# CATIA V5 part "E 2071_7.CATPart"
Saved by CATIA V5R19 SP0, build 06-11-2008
Nomenclature: E 2071_7
Description: PART-E 2071_7-DESC
Property "Hersteller": "Meusburger"
Property "Material": "St"
Property "Bestellnummer": "E 2071/7"
Property "Teilenummer": "E 2071/7"
Property "Beschreibung": "Kugelverschlussstopfen _ Expander sealing plug"
Material "Steel": density 7860 kg/m3, Young's modulus 2e+11 Pa, Poisson ratio 0.266, thermal expansion 1.17e-05 1/K
Bounding box of the stored display mesh (mm): x -3.5 to 3.5, y -3.49 to 3.49, z 0 to 7.5
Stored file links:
  G:\UTB\Kombinované\Bakalářská práce\Catia\FORMA\E 2071_7.CATPart
  D:\Aplikace\CATIA\Nová složka\win_b64\startup\materials\Catalog.CATMaterial
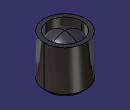
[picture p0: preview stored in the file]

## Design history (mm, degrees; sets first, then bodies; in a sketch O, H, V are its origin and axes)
Body1 "E 2071_7" (main body)
  Solid1: solid without history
